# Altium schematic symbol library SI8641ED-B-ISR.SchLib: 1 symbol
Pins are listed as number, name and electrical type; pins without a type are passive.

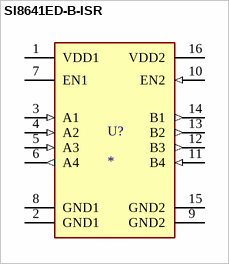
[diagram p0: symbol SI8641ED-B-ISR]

## SI8641ED-B-ISR
designator U?
General Purpose Digital Isolator 2500Vrms 4 Channel 150Mbps 35kV/Âµs CMTI 16-SOIC _0.154, 3.90mm Width_; MP: SI8641BB-B-IS1; MF: Silicon Labs
footprint SI8641ED-B-ISR
pins: 1 VDD1 (power), 2 GND1 (power), 3 A1 (in), 4 A2 (in), 5 A3 (in), 6 A4 (out), 7 EN1 (power), 8 GND1 (power), 9 GND2 (power), 10 EN2 (in), 11 B4 (in), 12 B3 (out), 13 B2 (out), 14 B1 (out), 15 GND2 (power), 16 VDD2 (power)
